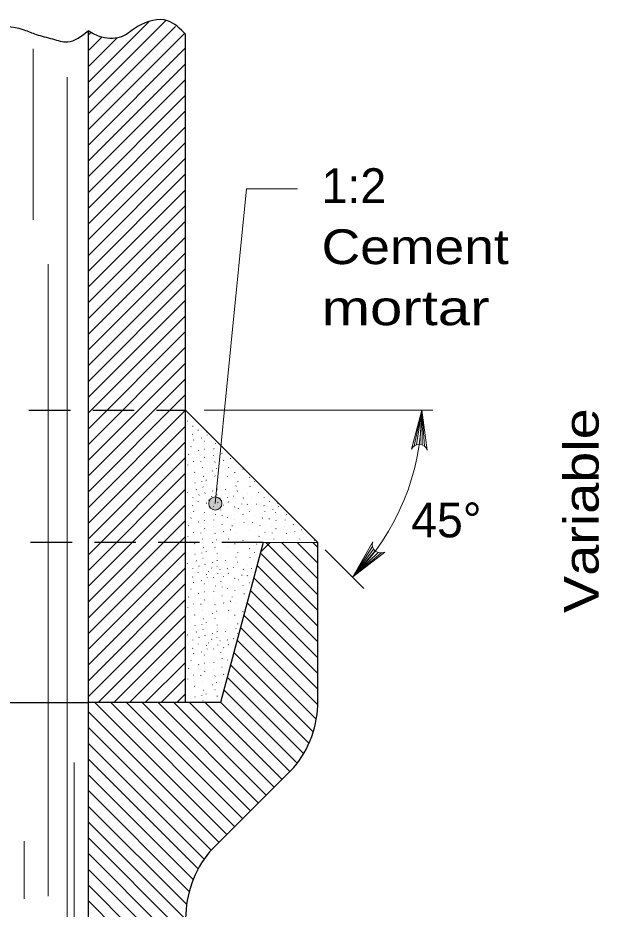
# Model space of a CAD drawing. Extents: x 1302.9 to 1336.9, y 688.5 to 710.5.
# Drawn here: x 1311.828 to 1314.436, y 699.122 to 703.12 of the extents above; entities that cross this region are included whole.
import ezdxf

# ---------------------------------------------------------------- set-up
doc = ezdxf.new("R2010")
doc.units = 0
doc.header["$LTSCALE"] = 0.062
doc.linetypes.add('MEDIUM_DASHED', pattern=[4.5, 3, -1.5])
doc.layers.add('1', color=7, linetype='Continuous', lineweight=13)

msp = doc.modelspace()

# ---------------------------------------------------------------- hatches: boundary and pattern name
at = {"layer": '1'}
msp.add_hatch(color=256, dxfattribs=at).paths.add_polyline_path([(1312.7436, 700.94181, 1), (1312.6846, 700.94181, 1)])

# ---------------------------------------------------------------- linework, layer by layer
for p, q in [((1312.14367, 702.75983), (1312.49433, 703.1105)), ((1312.14367, 702.83058), (1312.41767, 703.1045)), ((1312.14367, 702.68925), (1312.53517, 703.08067)), ((1312.14367, 703.0425), (1312.15617, 703.05517)), ((1312.14367, 702.6185), (1312.57558, 703.05042)), ((1312.14367, 702.97192), (1312.20517, 703.03333)), ((1312.14367, 702.90117), (1312.27342, 703.03092)), ((1311.8975, 702.98067), (1311.8975, 702.2135)), ((1312.14367, 702.54783), (1312.58092, 702.98508)), ((1312.14367, 702.47717), (1312.58092, 702.91442)), ((1312.04967, 698.46067), (1312.04967, 702.85392)), ((1312.14367, 702.4065), (1312.58092, 702.84375)), ((1312.14367, 702.33583), (1312.58092, 702.77308)), ((1312.14367, 702.26517), (1312.58092, 702.70242)), ((1312.14367, 702.1945), (1312.58092, 702.63175)), ((1312.14367, 702.12383), (1312.58092, 702.56108)), ((1312.14367, 702.05317), (1312.58092, 702.49042)), ((1312.14367, 701.9825), (1312.58092, 702.41975)), ((1312.14367, 701.91183), (1312.58092, 702.34908)), ((1312.14367, 701.84117), (1312.58092, 702.27842)), ((1312.14367, 701.7705), (1312.58092, 702.20775)), ((1312.14367, 701.69983), (1312.58092, 702.13708)), ((1312.14367, 701.62917), (1312.58092, 702.06642)), ((1311.964, 702.01592), (1311.964, 699.18083)), ((1312.14367, 701.5585), (1312.58092, 701.99575)), ((1312.14367, 701.48783), (1312.58092, 701.92508)), ((1312.14367, 701.41717), (1312.58092, 701.85442)), ((1312.14367, 701.34642), (1312.58092, 701.78367)), ((1312.14367, 701.27575), (1312.58092, 701.713)), ((1312.14367, 701.20508), (1312.58092, 701.64233)), ((1312.14367, 701.13442), (1312.58092, 701.57167)), ((1312.14367, 701.06375), (1312.58092, 701.501)), ((1312.14367, 700.99308), (1312.58092, 701.43033)), ((1312.14367, 700.92242), (1312.58092, 701.35967)), ((1313.69067, 701.36), (1312.66425, 701.36)), ((1313.60608, 701.19967), (1313.64058, 701.36)), ((1313.61683, 701.20517), (1313.64058, 701.36)), ((1313.63142, 701.20708), (1313.64058, 701.36)), ((1313.64258, 701.20475), (1313.64058, 701.36)), ((1313.65333, 701.19867), (1313.64058, 701.36)), ((1312.14367, 700.85175), (1312.58092, 701.289)), ((1312.58925, 701.31058), (1312.58842, 701.31142)), ((1312.61358, 701.28767), (1312.61408, 701.28933)), ((1312.64067, 701.29933), (1312.64092, 701.3)), ((1312.61325, 701.25142), (1312.61242, 701.25225)), ((1312.63683, 701.26975), (1312.63742, 701.27142)), ((1312.67408, 701.26208), (1312.67458, 701.26375)), ((1312.67717, 701.24808), (1312.67775, 701.24975)), ((1312.14367, 700.78108), (1312.58092, 701.21833)), ((1312.61667, 701.22617), (1312.61717, 701.22783)), ((1312.65233, 701.23475), (1312.65292, 701.23633)), ((1312.66567, 701.22142), (1312.66392, 701.22108)), ((1312.71525, 701.21117), (1312.71442, 701.212)), ((1312.59417, 701.16117), (1312.59475, 701.16283)), ((1312.60592, 701.19667), (1312.60425, 701.19633)), ((1312.63917, 701.17742), (1312.63967, 701.17908)), ((1312.66725, 701.18508), (1312.6655, 701.18467)), ((1312.707, 701.186), (1312.70758, 701.18767)), ((1312.74475, 701.16633), (1312.74392, 701.16717)), ((1312.14367, 700.71042), (1312.58092, 701.14767)), ((1312.61833, 701.13092), (1312.61667, 701.13058)), ((1312.64658, 701.15625), (1312.64575, 701.15708)), ((1312.64925, 701.12883), (1312.64975, 701.1305)), ((1312.66633, 701.1475), (1312.66683, 701.14917)), ((1312.70642, 701.15608), (1312.70558, 701.15692)), ((1312.71392, 701.12792), (1312.71225, 701.12708)), ((1312.75175, 701.13458), (1312.75092, 701.13542)), ((1312.78317, 701.14333), (1312.7815, 701.14292)), ((1312.59025, 701.11333), (1312.59083, 701.115)), ((1312.62133, 701.08083), (1312.62183, 701.0825)), ((1312.6575, 701.10217), (1312.65667, 701.103)), ((1312.70308, 701.088), (1312.70142, 701.08717)), ((1312.71892, 701.098), (1312.71808, 701.09883)), ((1312.77375, 701.10092), (1312.77425, 701.10258)), ((1312.80258, 701.08075), (1312.80083, 701.08033)), ((1312.83808, 701.09475), (1312.83867, 701.09642)), ((1312.14367, 700.63975), (1312.58092, 701.077)), ((1312.66333, 701.06367), (1312.66158, 701.06333)), ((1312.6725, 701.0455), (1312.67308, 701.04717)), ((1312.71308, 701.06475), (1312.71225, 701.06558)), ((1312.76958, 701.0635), (1312.76875, 701.06433)), ((1312.81483, 701.04058), (1312.81542, 701.04225)), ((1312.86825, 701.05842), (1312.86883, 701.06008)), ((1312.88992, 701.04058), (1312.8905, 701.04225)), ((1312.14367, 700.56908), (1312.58092, 701.00633)), ((1312.62375, 701.03425), (1312.62208, 701.03392)), ((1312.62908, 701.00342), (1312.62958, 701.00508)), ((1312.65308, 701.03825), (1312.65367, 701.03992)), ((1312.65975, 701.0155), (1312.65892, 701.01633)), ((1312.7235, 701.00642), (1312.72175, 701.00608)), ((1312.7225, 701.03592), (1312.72308, 701.03758)), ((1312.75975, 701.005), (1312.76033, 701.00667)), ((1312.808, 701.02033), (1312.80625, 701.02)), ((1312.87075, 701.01883), (1312.869, 701.01842)), ((1312.58925, 700.99075), (1312.58842, 700.99158)), ((1312.61358, 700.96792), (1312.61408, 700.96958)), ((1312.64067, 700.97958), (1312.64125, 700.98125)), ((1312.66783, 700.98833), (1312.66842, 700.98992)), ((1312.69808, 700.97167), (1312.69725, 700.9725)), ((1312.70308, 700.99742), (1312.70225, 700.99817)), ((1312.72225, 700.98), (1312.72142, 700.98083)), ((1312.73558, 700.965), (1312.73475, 700.96583)), ((1312.76892, 700.96833), (1312.76808, 700.96917)), ((1312.79725, 700.97417), (1312.79642, 700.975)), ((1312.81417, 700.99792), (1312.8125, 700.99758)), ((1312.84058, 700.96667), (1312.83892, 700.96583)), ((1312.85725, 700.98742), (1312.85642, 700.98833)), ((1312.87717, 700.96833), (1312.87633, 700.96917)), ((1312.90908, 700.99075), (1312.90825, 700.99158)), ((1312.93342, 700.96792), (1312.93392, 700.96958)), ((1312.95267, 700.98458), (1312.95683, 700.983)), ((1312.9605, 700.97958), (1312.96075, 700.98025)), ((1312.14367, 700.49842), (1312.58092, 700.93567)), ((1312.61325, 700.93158), (1312.61242, 700.93242)), ((1312.63683, 700.94992), (1312.63742, 700.95158)), ((1312.67408, 700.94225), (1312.67458, 700.94392)), ((1312.68408, 700.95667), (1312.68483, 700.95633)), ((1312.68483, 700.95633), (1312.68517, 700.95592)), ((1312.70625, 700.928), (1312.70683, 700.92967)), ((1312.72567, 700.94533), (1312.72625, 700.947)), ((1312.75175, 700.93392), (1312.75092, 700.93475)), ((1312.77217, 700.94683), (1312.77275, 700.9485)), ((1312.80083, 700.92492), (1312.80142, 700.92658)), ((1312.83267, 700.93908), (1312.83325, 700.94075)), ((1312.8575, 700.93733), (1312.858, 700.939)), ((1312.89867, 700.93875), (1312.89692, 700.93833)), ((1312.93308, 700.93158), (1312.93225, 700.93242)), ((1312.95667, 700.94992), (1312.95725, 700.95158)), ((1312.99392, 700.94225), (1312.99442, 700.94392)), ((1312.997, 700.92825), (1312.99758, 700.92992)), ((1312.61667, 700.90633), (1312.61717, 700.908)), ((1312.66567, 700.90158), (1312.66392, 700.90125)), ((1312.71525, 700.89133), (1312.71442, 700.89217)), ((1312.73883, 700.911), (1312.73942, 700.91267)), ((1312.7455, 700.88667), (1312.74467, 700.8875)), ((1312.81767, 700.91842), (1312.81683, 700.91925)), ((1312.83858, 700.89292), (1312.83775, 700.89375)), ((1312.86917, 700.9055), (1312.86742, 700.90508)), ((1312.892, 700.889), (1312.89117, 700.88983)), ((1312.9365, 700.90633), (1312.937, 700.908)), ((1312.97217, 700.91492), (1312.97275, 700.9165)), ((1312.9855, 700.90158), (1312.98375, 700.90125)), ((1313.03517, 700.89133), (1313.03433, 700.89217)), ((1312.14367, 700.42775), (1312.58092, 700.865)), ((1312.59417, 700.84133), (1312.59475, 700.84308)), ((1312.60592, 700.87683), (1312.60425, 700.8765)), ((1312.63917, 700.85758), (1312.63967, 700.85925)), ((1312.66725, 700.86525), (1312.6655, 700.86483)), ((1312.707, 700.86617), (1312.70758, 700.86783)), ((1312.74475, 700.8465), (1312.74392, 700.84733)), ((1312.76908, 700.8785), (1312.76958, 700.88017)), ((1312.78925, 700.84067), (1312.78975, 700.84225)), ((1312.80208, 700.86967), (1312.80125, 700.8705)), ((1312.8435, 700.85533), (1312.84408, 700.857)), ((1312.88083, 700.85675), (1312.87908, 700.85633)), ((1312.914, 700.84133), (1312.91458, 700.84308)), ((1312.92575, 700.87683), (1312.92408, 700.8765)), ((1312.95542, 700.872), (1312.95592, 700.87367)), ((1312.98708, 700.86525), (1312.98533, 700.86483)), ((1313.02692, 700.86617), (1313.0275, 700.86783)), ((1313.06458, 700.8465), (1313.06375, 700.84733)), ((1312.61833, 700.81117), (1312.61667, 700.81083)), ((1312.64658, 700.8365), (1312.64575, 700.83733)), ((1312.64925, 700.809), (1312.64975, 700.81067)), ((1312.66633, 700.82775), (1312.66683, 700.82942)), ((1312.70642, 700.83633), (1312.70558, 700.83717)), ((1312.71392, 700.80808), (1312.71225, 700.80725)), ((1312.75175, 700.81483), (1312.75092, 700.81567)), ((1312.78317, 700.82358), (1312.7815, 700.82317)), ((1312.80983, 700.8125), (1312.809, 700.81333)), ((1312.8695, 700.82025), (1312.86867, 700.82108)), ((1312.93817, 700.81117), (1312.9365, 700.81083)), ((1312.96642, 700.8365), (1312.96558, 700.83733)), ((1312.96908, 700.809), (1312.96958, 700.81067)), ((1312.98617, 700.82775), (1312.98667, 700.82942)), ((1313.02633, 700.83633), (1313.0255, 700.83717)), ((1313.03383, 700.80808), (1313.03217, 700.80725)), ((1313.07158, 700.81483), (1313.07075, 700.81567)), ((1313.103, 700.82358), (1313.10133, 700.82317)), ((1312.14367, 700.35708), (1312.58092, 700.79433)), ((1312.59025, 700.7935), (1312.59083, 700.79517)), ((1312.62133, 700.761), (1312.62183, 700.76267)), ((1312.6575, 700.78233), (1312.65667, 700.78317)), ((1312.70308, 700.76817), (1312.70142, 700.76733)), ((1312.71892, 700.77817), (1312.71808, 700.779)), ((1312.77375, 700.78108), (1312.77425, 700.78275)), ((1312.80258, 700.76092), (1312.80083, 700.7605)), ((1312.83808, 700.77492), (1312.83867, 700.77658)), ((1312.91008, 700.7935), (1312.91067, 700.79517)), ((1312.91842, 700.7245), (1312.9605, 700.76658)), ((1313.17442, 700.76658), (1312.92967, 700.76658)), ((1313.17442, 700.53258), (1312.94033, 700.76658)), ((1312.97733, 700.78233), (1312.9765, 700.78317)), ((1313.17442, 700.60317), (1313.011, 700.76658)), ((1313.023, 700.76817), (1313.02133, 700.76733)), ((1313.03883, 700.77817), (1313.038, 700.779)), ((1313.17442, 700.67392), (1313.08167, 700.76658)), ((1313.09358, 700.78108), (1313.09408, 700.78275)), ((1313.17442, 700.7445), (1313.15233, 700.76658)), ((1313.15792, 700.77492), (1313.1585, 700.77658)), ((1312.14367, 700.28642), (1312.58092, 700.72367)), ((1312.66333, 700.74383), (1312.66158, 700.7435)), ((1312.6725, 700.72567), (1312.67308, 700.72733)), ((1312.71308, 700.74492), (1312.71225, 700.74575)), ((1312.76958, 700.74367), (1312.76875, 700.7445)), ((1312.81483, 700.72075), (1312.81542, 700.72242)), ((1312.86825, 700.73858), (1312.86883, 700.74025)), ((1312.88992, 700.72075), (1312.8905, 700.72242)), ((1312.899, 700.75908), (1312.89817, 700.75992)), ((1313.20725, 700.73375), (1313.38008, 700.56092)), ((1313.41917, 700.74867), (1313.33192, 700.61242)), ((1313.42408, 700.73725), (1313.33192, 700.61242)), ((1313.43158, 700.72867), (1313.33192, 700.61242)), ((1313.44442, 700.72142), (1313.33192, 700.61242)), ((1312.62375, 700.71442), (1312.62208, 700.71408)), ((1312.62908, 700.68367), (1312.62958, 700.68533)), ((1312.65308, 700.71842), (1312.65367, 700.72008)), ((1312.65975, 700.69575), (1312.65892, 700.6965)), ((1312.7235, 700.68667), (1312.72175, 700.68633)), ((1312.7225, 700.71608), (1312.72308, 700.71775)), ((1312.75975, 700.68525), (1312.76033, 700.68692)), ((1312.808, 700.7005), (1312.80625, 700.70017)), ((1312.87075, 700.69908), (1312.869, 700.69867)), ((1313.17442, 700.46183), (1312.917, 700.71925)), ((1313.45625, 700.71933), (1313.33192, 700.61242)), ((1312.14367, 700.21575), (1312.58092, 700.653)), ((1312.58925, 700.671), (1312.58842, 700.67183)), ((1312.61358, 700.64808), (1312.61408, 700.64975)), ((1312.64067, 700.65975), (1312.64125, 700.66142)), ((1312.66783, 700.6685), (1312.66842, 700.67017)), ((1312.69808, 700.65183), (1312.69725, 700.65267)), ((1312.70308, 700.67767), (1312.70225, 700.67842)), ((1312.72225, 700.66017), (1312.72142, 700.661)), ((1312.73558, 700.64517), (1312.73475, 700.646)), ((1312.76892, 700.6485), (1312.76808, 700.64933)), ((1312.79725, 700.65433), (1312.79642, 700.65517)), ((1312.81417, 700.67817), (1312.8125, 700.67783)), ((1312.84058, 700.64683), (1312.83892, 700.646)), ((1312.85725, 700.66767), (1312.85642, 700.6685)), ((1312.87717, 700.6485), (1312.87633, 700.64933)), ((1313.17442, 700.39125), (1312.902, 700.6635)), ((1312.61325, 700.61175), (1312.61242, 700.61258)), ((1312.63683, 700.63008), (1312.63742, 700.63175)), ((1312.67408, 700.62242), (1312.67458, 700.62408)), ((1312.67717, 700.60842), (1312.67775, 700.61008)), ((1312.68408, 700.63683), (1312.68483, 700.6365)), ((1312.68483, 700.6365), (1312.68517, 700.63608)), ((1312.70625, 700.60817), (1312.70683, 700.60983)), ((1312.72567, 700.6255), (1312.72625, 700.62717)), ((1312.75175, 700.61408), (1312.75092, 700.61492)), ((1312.77217, 700.627), (1312.77275, 700.62867)), ((1312.80083, 700.60508), (1312.80142, 700.60675)), ((1312.83267, 700.61925), (1312.83325, 700.62092)), ((1312.8575, 700.6175), (1312.858, 700.61917)), ((1313.17442, 700.3205), (1312.88708, 700.60775)), ((1312.14367, 700.14508), (1312.58092, 700.58233)), ((1312.61667, 700.5865), (1312.61717, 700.58817)), ((1312.65233, 700.59508), (1312.65292, 700.59667)), ((1312.66567, 700.58175), (1312.66392, 700.58142)), ((1312.71525, 700.5715), (1312.71442, 700.57233)), ((1312.73883, 700.59117), (1312.73942, 700.59283)), ((1312.7455, 700.56683), (1312.74467, 700.56767)), ((1312.81767, 700.59858), (1312.81683, 700.59942)), ((1312.83858, 700.57308), (1312.83775, 700.57392)), ((1312.86917, 700.58567), (1312.86742, 700.58525)), ((1312.59417, 700.52158), (1312.59475, 700.52325)), ((1312.60592, 700.557), (1312.60425, 700.55667)), ((1312.63917, 700.53783), (1312.63967, 700.5395)), ((1312.66725, 700.5455), (1312.6655, 700.54508)), ((1312.707, 700.54642), (1312.70758, 700.54808)), ((1312.74475, 700.52675), (1312.74392, 700.52758)), ((1312.76908, 700.55867), (1312.76958, 700.56033)), ((1312.78925, 700.52083), (1312.78975, 700.5225)), ((1312.80208, 700.54983), (1312.80125, 700.55075)), ((1312.8435, 700.53558), (1312.84408, 700.53725)), ((1313.17442, 700.24992), (1312.87217, 700.55208)), ((1312.14367, 700.07442), (1312.58092, 700.51167)), ((1312.61833, 700.49133), (1312.61667, 700.491)), ((1312.64658, 700.51667), (1312.64575, 700.5175)), ((1312.64925, 700.48917), (1312.64975, 700.49083)), ((1312.66633, 700.50792), (1312.66683, 700.50958)), ((1312.70642, 700.5165), (1312.70558, 700.51733)), ((1312.71392, 700.48825), (1312.71225, 700.48742)), ((1312.75175, 700.495), (1312.75092, 700.49583)), ((1312.78317, 700.50375), (1312.7815, 700.50333)), ((1312.80983, 700.49267), (1312.809, 700.4935)), ((1313.17442, 700.17917), (1312.85725, 700.49633)), ((1312.18817, 700.04825), (1312.58092, 700.44092)), ((1312.59025, 700.47367), (1312.59083, 700.47533)), ((1312.62133, 700.44117), (1312.62183, 700.44283)), ((1312.6575, 700.4625), (1312.65667, 700.46333)), ((1312.70308, 700.44833), (1312.70142, 700.4475)), ((1312.71892, 700.45833), (1312.71808, 700.45917)), ((1312.77375, 700.46125), (1312.77425, 700.46292)), ((1312.80258, 700.44108), (1312.80083, 700.44067)), ((1312.83808, 700.45508), (1312.83867, 700.45675)), ((1312.66333, 700.424), (1312.66158, 700.42367)), ((1312.6725, 700.40592), (1312.67308, 700.40758)), ((1312.71308, 700.42508), (1312.71225, 700.42592)), ((1312.76958, 700.42383), (1312.76875, 700.42467)), ((1312.81483, 700.401), (1312.81542, 700.40267)), ((1313.17442, 700.10858), (1312.84233, 700.44058)), ((1312.25883, 700.04825), (1312.58092, 700.37033)), ((1312.62375, 700.39467), (1312.62208, 700.39433)), ((1312.62908, 700.36383), (1312.62958, 700.3655)), ((1312.65308, 700.39867), (1312.65367, 700.40033)), ((1312.65975, 700.37592), (1312.65892, 700.37675)), ((1312.7235, 700.36683), (1312.72175, 700.3665)), ((1312.7225, 700.39633), (1312.72308, 700.398)), ((1312.75975, 700.36542), (1312.76033, 700.36708)), ((1312.808, 700.38075), (1312.80625, 700.38042)), ((1313.174, 700.03825), (1312.82733, 700.38492)), ((1312.58925, 700.35117), (1312.58842, 700.352)), ((1312.61358, 700.32825), (1312.61408, 700.32992)), ((1312.64067, 700.33992), (1312.64125, 700.34158)), ((1312.66783, 700.34867), (1312.66842, 700.35033)), ((1312.69808, 700.332), (1312.69725, 700.33283)), ((1312.70308, 700.35783), (1312.70225, 700.35858)), ((1312.72225, 700.34033), (1312.72142, 700.34117)), ((1312.73558, 700.32533), (1312.73475, 700.32617)), ((1312.76892, 700.32867), (1312.76808, 700.3295)), ((1312.79725, 700.3345), (1312.79642, 700.33533)), ((1313.16692, 699.97467), (1312.81242, 700.32908)), ((1312.81417, 700.35833), (1312.8125, 700.358)), ((1312.32958, 700.04825), (1312.58092, 700.29958)), ((1312.61325, 700.29192), (1312.61242, 700.29275)), ((1312.63683, 700.31025), (1312.63742, 700.31192)), ((1312.67408, 700.30258), (1312.67458, 700.30425)), ((1312.67717, 700.28858), (1312.67775, 700.29025)), ((1312.68408, 700.317), (1312.68483, 700.31667)), ((1312.68483, 700.31667), (1312.68517, 700.31625)), ((1312.70625, 700.28833), (1312.70683, 700.29)), ((1312.72567, 700.30567), (1312.72625, 700.30733)), ((1312.75175, 700.29425), (1312.75092, 700.29508)), ((1312.77217, 700.30717), (1312.77275, 700.30883)), ((1312.65233, 700.27525), (1312.65292, 700.27683)), ((1312.66567, 700.262), (1312.66392, 700.26158)), ((1312.71525, 700.25175), (1312.71442, 700.25258)), ((1312.73883, 700.27133), (1312.73942, 700.273)), ((1312.7455, 700.24708), (1312.74467, 700.24792)), ((1313.15325, 699.91767), (1312.7975, 700.27333)), ((1312.40017, 700.04825), (1312.58092, 700.229)), ((1312.59417, 700.20175), (1312.59475, 700.20342)), ((1312.60592, 700.23725), (1312.60425, 700.23692)), ((1312.63917, 700.218), (1312.63967, 700.21967)), ((1312.66725, 700.22567), (1312.6655, 700.22525)), ((1312.707, 700.22658), (1312.70758, 700.22825)), ((1312.74475, 700.20692), (1312.74392, 700.20775)), ((1312.76908, 700.23892), (1312.76958, 700.24058)), ((1313.13425, 699.866), (1312.7825, 700.21767)), ((1312.61833, 700.1715), (1312.61667, 700.17117)), ((1312.64658, 700.19683), (1312.64575, 700.19767)), ((1312.64925, 700.16933), (1312.64975, 700.171)), ((1312.66633, 700.18808), (1312.66683, 700.18975)), ((1312.70642, 700.19667), (1312.70558, 700.1975)), ((1312.71392, 700.16842), (1312.71225, 700.16758)), ((1312.75175, 700.17517), (1312.75092, 700.176)), ((1313.11008, 699.8195), (1312.76758, 700.16192)), ((1312.47092, 700.04825), (1312.58092, 700.15825)), ((1312.59025, 700.15383), (1312.59083, 700.1555)), ((1312.62133, 700.12133), (1312.62183, 700.123)), ((1312.6575, 700.14267), (1312.65667, 700.1435)), ((1312.70308, 700.1285), (1312.70142, 700.12767)), ((1312.71892, 700.1385), (1312.71808, 700.13933)), ((1312.5415, 700.04825), (1312.58092, 700.08767)), ((1312.66333, 700.10425), (1312.66158, 700.10392)), ((1312.6725, 700.08608), (1312.67308, 700.08775)), ((1312.71308, 700.10533), (1312.71225, 700.10617)), ((1313.08183, 699.777), (1312.75267, 700.10625)), ((1312.76633, 699.4565), (1312.1745, 700.04825)), ((1312.80167, 699.49183), (1312.24517, 700.04825)), ((1312.837, 699.52717), (1312.31592, 700.04825)), ((1312.87233, 699.56242), (1312.3865, 700.04825)), ((1312.90767, 699.59783), (1312.45725, 700.04825)), ((1312.943, 699.63317), (1312.52783, 700.04825)), ((1312.97833, 699.6685), (1312.59858, 700.04825)), ((1312.62375, 700.07483), (1312.62208, 700.0745)), ((1312.65308, 700.07883), (1312.65367, 700.0805)), ((1312.65975, 700.05608), (1312.65892, 700.05692)), ((1313.01375, 699.70383), (1312.66925, 700.04825)), ((1312.7225, 700.0765), (1312.72308, 700.07817)), ((1313.049, 699.73917), (1312.73767, 700.0505)), ((1312.731, 699.42108), (1312.14367, 700.00842)), ((1312.69567, 699.38583), (1312.14367, 699.93783)), ((1312.66458, 699.34625), (1312.14367, 699.86708)), ((1312.08167, 695.38725), (1312.08167, 699.7805)), ((1312.63775, 699.30242), (1312.14367, 699.79642)), ((1312.615, 699.25442), (1312.14367, 699.72575)), ((1312.59733, 699.20142), (1312.14367, 699.65508)), ((1312.58575, 699.14233), (1312.14367, 699.58442)), ((1312.58108, 699.07633), (1312.14367, 699.51375)), ((1312.58108, 699.00567), (1312.14367, 699.44308)), ((1311.85658, 699.42767), (1311.85658, 699.16825)), ((1312.58092, 698.93517), (1312.14367, 699.37242)), ((1312.58092, 698.8645), (1312.14367, 699.30175)), ((1312.58092, 698.79383), (1312.14367, 699.23108)), ((1312.58092, 698.72317), (1312.14367, 699.16042))]:
    msp.add_line(p, q, dxfattribs=at)
at = {"layer": '1', "lineweight": 25}
for p, q in [((1312.14367, 703.06167), (1312.14367, 700.04825)), ((1312.58092, 700.04825), (1312.58092, 703.0465)), ((1312.58092, 701.36), (1313.17442, 700.76658)), ((1313.17442, 700.05567), (1313.17442, 700.76658)), ((1312.61667, 700.26667), (1312.61717, 700.26833)), ((1307.73933, 700.04825), (1312.14367, 700.04825)), ((1312.6885, 699.37875), (1313.06692, 699.75708))]:
    msp.add_line(p, q, dxfattribs=at)
at = {"layer": '1', "linetype": 'MEDIUM_DASHED', "lineweight": 25}
for p, q in [((1307.30208, 701.36), (1312.58092, 701.36)), ((1312.92967, 700.76658), (1306.95333, 700.76658))]:
    msp.add_line(p, q, dxfattribs=at)
at = {"layer": '1'}
for points in [[(1312.71408, 700.94183), (1312.85358, 702.353), (1313.08283, 702.353)], [(1313.59458, 701.18542), (1313.64058, 701.36), (1313.66525, 701.18117)], [(1313.474, 700.72375), (1313.33192, 700.61242), (1313.42025, 700.76983)]]:
    msp.add_lwpolyline(points, dxfattribs=at)
at = {"layer": '1', "lineweight": 25}
msp.add_lwpolyline([(1312.92967, 700.76658), (1312.73708, 700.04825), (1312.58092, 700.04825), (1312.14367, 700.04825), (1312.14367, 692.86483), (1312.58092, 692.86483)], dxfattribs=at)
at = {"layer": '1'}
msp.add_circle((1312.7141, 700.94181), 0.0295, dxfattribs=at)
for centre, radius, start, end in [((1312.58092, 701.35999), 1.05969, 315.12948, 0), ((1313.62913, 701.16904), 0.0382, 18.63434, 154.46046), ((1313.4564, 700.75764), 0.0382, 161.48422, 297.31035)]:
    msp.add_arc(centre, radius, start, end, dxfattribs=at)
at = {"layer": '1', "lineweight": 25}
for centre, major_axis in [((1312.70587, 700.05566), (-0.46853, 0)), ((1313.04962, 699.08014), (0.46853, 0))]:
    msp.add_ellipse(centre, major_axis=major_axis, ratio=0.999895, start_param=2.4506156, end_param=3.1415927, dxfattribs=at)
for points in [[(1312.58092, 703.0465), (1312.50025, 703.10683), (1312.36775, 703.08225), (1312.29908, 703.038), (1312.20583, 703.03308), (1312.14367, 703.0615)], [(1307.73933, 703.06167), (1307.83508, 703.09325), (1308.00375, 703.1), (1308.21292, 703.07975), (1308.57042, 703.03917), (1308.9415, 703.0595), (1309.23158, 703.07975), (1309.52842, 703.0595), (1309.81175, 703.05267), (1310.09508, 703.073), (1310.43242, 703.06625), (1310.59433, 703.04592), (1310.85075, 703.03242), (1311.20825, 703.03917), (1311.47808, 703.07975), (1311.66025, 703.0865), (1311.85592, 703.06625), (1311.90992, 703.04592), (1311.98408, 703.02567), (1312.05158, 703.01225), (1312.14367, 703.0615)]]:
    msp.add_spline(points, degree=3, dxfattribs=at)

# ---------------------------------------------------------------- texts
at = {"layer": '1'}
for s, p in [('1:2', (1313.191, 702.28942)), ('45°', (1313.59267, 700.78975))]:
    msp.add_text(s, height=0.156, dxfattribs=at).set_placement(p)
for s, width, p in [('Cement', 1.15, (1313.191, 702.01542)), ('mortar', 1.25, (1313.191, 701.74142))]:
    msp.add_text(s, height=0.156, dxfattribs=dict(at, width=width)).set_placement(p)
at = {"layer": '1', "width": 1.2}
msp.add_text('Variable', height=0.156, rotation=90, dxfattribs=at).set_placement((1314.43408, 700.45017))

doc.saveas('drawing.dxf')
